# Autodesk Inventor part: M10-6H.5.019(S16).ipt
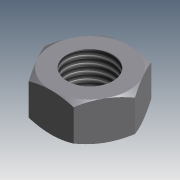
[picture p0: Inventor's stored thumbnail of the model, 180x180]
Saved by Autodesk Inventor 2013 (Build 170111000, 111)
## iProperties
Shininess: 0.0
Length Units: 11269
Angle Units: 11279
Time Units: 11290
Mass Units: 11283
Length Display Precision: 3
Angle Display Precision: 2
Created: 2001-04
Part Number: M10-6H.5.019(S16).ipt
Material: Steel, Mild
Document SubType Name: Modeling
Designer: tevgeniy
Mass: 11.2552 g
Surface Area: 10.7859 cm^2
Volume: 1.43196 cm^3
Density: 7.86 g/cm^3
Density: 0.0
Volumn: 0.0
Area: 0.0
PropertySet Name: Model Information
Control State: 0
Master: False
Checked Out: True
Checked Out Date: 2008-10-15
Last Check In Date: 2008-10-15
Author: tevgeniy
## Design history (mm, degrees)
node "ExtrusionBlind1" dims "d6" = 8.4, "d7" = 0
  sketch "Sketch1"
    geometry: L1 (484.39, 469.325)-(474.575, 469.325); L2 (489.297, 460.825)-(484.39, 469.325); L3 (484.39, 452.325)-(489.297, 460.825); L4 (474.575, 452.325)-(484.39, 452.325); L5 (469.667, 460.825)-(474.575, 452.325); L6 (474.575, 469.325)-(469.667, 460.825); C1 r 8.5 at (479.482, 460.825)
    constraints: 12 end point, 6 tangent, 3 parallel, 1 centre point, 1 horizontal, 1 other
    dimensions: "d1" = 120 deg angle of L1 L2; "d3" = 120 deg angle of L5 L6; "d5" = 17 diameter of C1; "d27" = 17 distance between parallel lines of L4 L1 (derived)
node "ExtrusionThru1" dims "d14" = 0.13, "d15" = 0
  sketch "Sketch2"
    geometry: L1 (-472.982, -455.084)-(-472.482, -455.95); L2 (-479.377, -452.325)-(-478.377, -452.325); L3 (-489.203, -460.662)-(-488.703, -459.796); C1 r 5 at (-479.482, -460.825); C2 r 8.5 at (-479.482, -460.825)
    constraints: 6 end point, 3 tangent, 2 centre point, 1 coincident
    dimensions: "d13" = 10 diameter of C1
node "WorkAxis1"
node "WorkPlane1"
node "RevolutionAngle1" dims "d24" = 360 deg
  sketch "Sketch3"
    geometry: L1 (0, 0)-(0, 8.4); L2 (8.5, 0)-(0, 0); L3 (9.815, 0.759)-(8.5, 0); L4 (9.815, 7.641)-(9.815, 0.759); L5 (8.5, 8.4)-(9.815, 7.641); L6 (0, 8.4)-(8.5, 8.4); L7 (0, 8.4)-(-1, 8.4); L8 (-0.105, 0)-(-1.105, 0); L9 (9.815, 8.4)-(9.815, 7.4); L10 (0, 17.846)-(0, -9.446); L11 (0, 17.846)-(0, -9.446)
    constraints: 22 end point, 4 collinear, 2 horizontal, 2 vertical
    dimensions: "d17" = 8.5 distance of L1.end L5.start; "d19" = 30 deg angle of L6 L5; "d21" = 30 deg angle of L3 L2; "d23" = 0 horizontal distance of L5.start L2.start
thread "Thread1" dims "d25" = 10, "d26" = 0
body "Solid1"
other parameters: "d0" = 120 deg (derived), "d2" = 120 deg (derived), "d4" = 17 (derived), "d8" = 0, "d9" = 0, "d10" = 0, "d11" = 0, "d16" = 8.5 (derived), "d18" = 30 deg (derived), "d20" = 30 deg (derived), "d22" = 0 (derived), "d28" = 0
